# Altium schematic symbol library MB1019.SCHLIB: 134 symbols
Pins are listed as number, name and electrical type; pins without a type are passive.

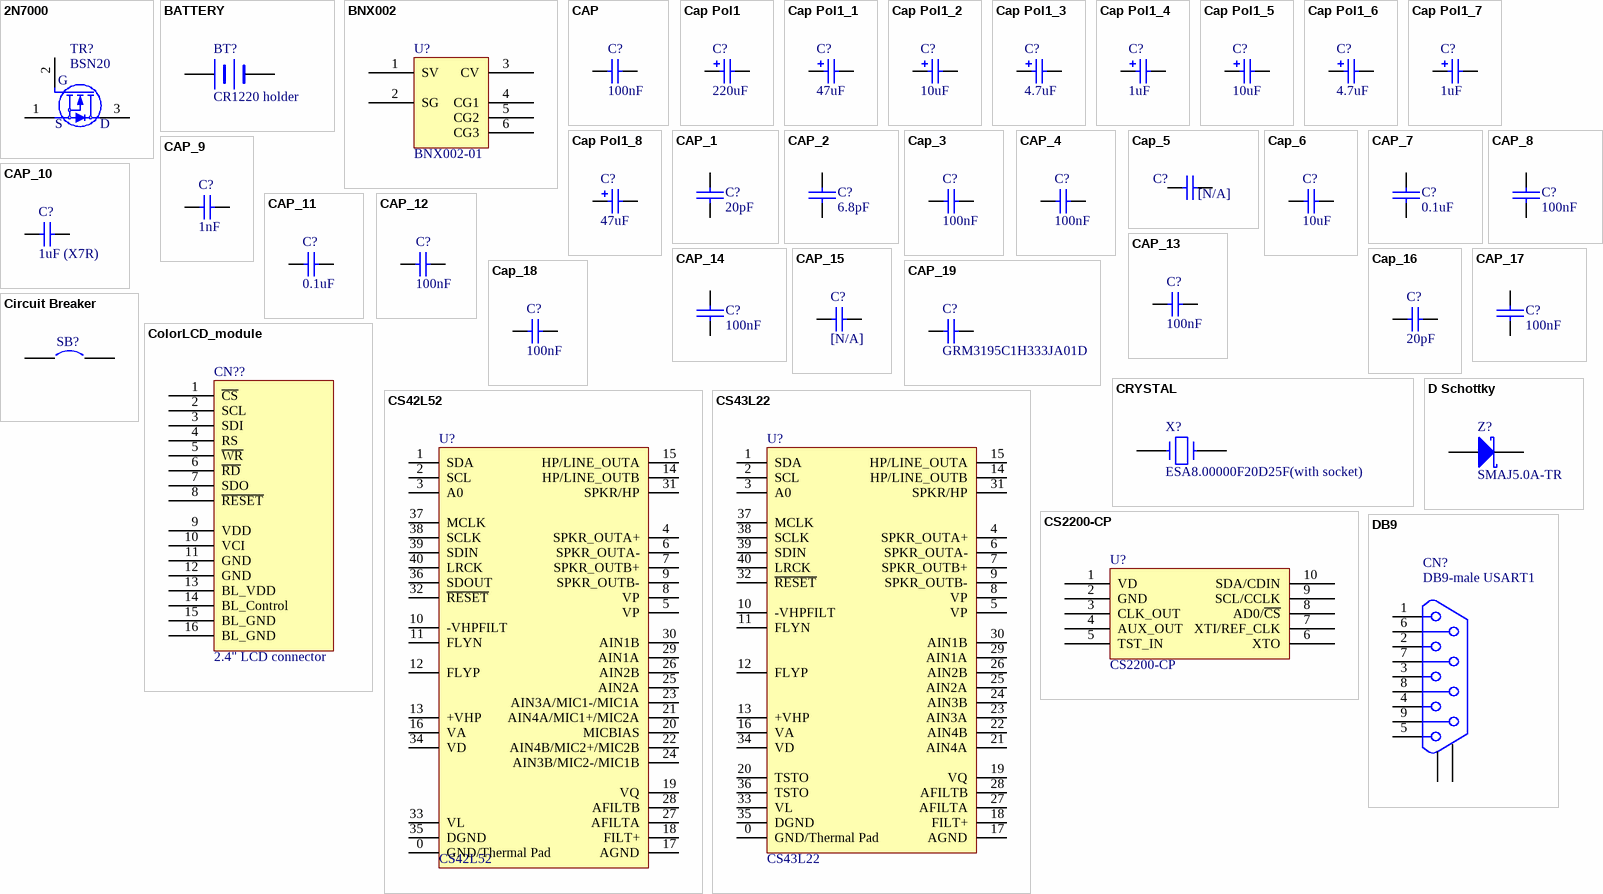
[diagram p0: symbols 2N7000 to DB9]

## 2N7000
designator TR?, comment BSN20
footprint SOT23-3L (Footprint not found)
footprint SOT-23
pins: 1 S, 2 G, 3 D

## BATTERY
designator BT?, comment CR1220 holder
Battery
footprint BATT (Footprint not found)
footprint LI1220_1
pins: 1 +, 2 -
2 alternate drawings of the same symbol

## BNX002
designator U?, comment BNX002-01
footprint BNX001 (Footprint not found)
pins: 1 SV, 2 SG, 3 CV, 4 CG1, 5 CG2, 6 CG3

## CAP
designator C?, comment 100nF
Capacitor; Value: 100pF
footprint RAD-0.3 (Capacitor; 2 Leads)
simulation model CAP (Capacitor)
signal-integrity model Cap
footprint CAPR5.08-7.8X3.2
footprint CAPR2.54-5.1X3.2
footprint 0603
footprint 0603P
footprint 0603C
footprint 0402C
pins: 1, 2

## Cap Pol1
designator C?, comment 220uF
Polarized Capacitor (Radial); Value: 47uF
simulation model CAP (Capacitor)
signal-integrity model C310M
footprint C310M (Footprint not found)
pins: 1, 2

## Cap Pol1_1
designator C?, comment 47uF
Polarized Capacitor (Radial); Value: 10uF
simulation model CAP (Capacitor)
signal-integrity model C200M
footprint C200M (Footprint not found)
pins: 1, 2

## Cap Pol1_2
designator C?, comment 10uF
Polarized Capacitor (Radial)
simulation model CAP (Capacitor)
signal-integrity model C200M
footprint 3528 (Footprint not found)
footprint TAN-A
pins: 1, 2

## Cap Pol1_3
designator C?, comment 4.7uF
Polarized Capacitor (Radial); Value: 100pF
simulation model CAP (Capacitor)
signal-integrity model Cap Pol
footprint Model Name (Footprint not found)
footprint TAN-A
pins: 1, 2

## Cap Pol1_4
designator C?, comment 1uF
Polarized Capacitor (Radial); Value: 10uF
simulation model CAP (Capacitor)
signal-integrity model Cap Pol
footprint 3528 (Footprint not found)
footprint TAN-B
footprint TAN-A
pins: 1, 2

## Cap Pol1_5
designator C?, comment 10uF
Polarized Capacitor (Radial)
simulation model CAP (Capacitor)
signal-integrity model C200M
footprint 3528 (Footprint not found)
footprint TAN-B
footprint TAN-A
pins: 1, 2

## Cap Pol1_6
designator C?, comment 4.7uF
Polarized Capacitor (Radial); Value: 100pF
simulation model CAP (Capacitor)
signal-integrity model 3528A
footprint 3528 (Footprint not found)
footprint TAN-B
footprint TAN-A
pins: 1, 2

## Cap Pol1_7
designator C?, comment 1uF
Polarized Capacitor (Radial); Value: 47uF
simulation model CAP (Capacitor)
signal-integrity model C310M
footprint C310M (Footprint not found)
footprint C160M
footprint TAN-A
pins: 1, 2

## Cap Pol1_8
designator C?, comment 47uF
Polarized Capacitor (Radial); Value: 100pF
simulation model CAP (Capacitor)
signal-integrity model Cap Pol
footprint TAN-B (Footprint not found)
pins: 1, 2

## CAP_1
designator C?, comment 20pF
Capacitor
footprint 0603 (Footprint not found)
footprint 0603C
pins: 1, 2
2 alternate drawings of the same symbol

## CAP_2
designator C?, comment 6.8pF
Capacitor
footprint 0603 (Footprint not found)
footprint 0603C
pins: 1, 2

## Cap_3
designator C?, comment 100nF
Capacitor; Value: 10nF
simulation model CAP (Capacitor)
signal-integrity model Cap
footprint 0603 (Footprint not found)
footprint 0402C
footprint 0603C
pins: 1, 2

## CAP_4
designator C?, comment 100nF
Capacitor; Value: 100pF
footprint RAD-0.3 (Capacitor; 2 Leads)
simulation model CAP (Capacitor)
signal-integrity model Cap
footprint CAPR5.08-7.8X3.2
footprint CAPR2.54-5.1X3.2
footprint 0603
footprint 0402C
footprint 0603C
pins: 1, 2

## Cap_5
designator C?, comment [N/A]
Capacitor; Value: 10nF
simulation model CAP (Capacitor)
signal-integrity model Cap
footprint 0603 (Footprint not found)
footprint 0603C (Footprint not found)
pins: 1, 2

## Cap_6
designator C?, comment 10uF
Capacitor; Value: 10nF
simulation model CAP (Capacitor)
signal-integrity model Cap
footprint 0603 (Footprint not found)
footprint 0402C
footprint 0805C (Footprint not found)
pins: 1, 2

## CAP_7
designator C?, comment 0.1uF
Capacitor
footprint 0603 (Footprint not found)
footprint 0603P
footprint 0603C (Footprint not found)
pins: 1, 2
2 alternate drawings of the same symbol

## CAP_8
designator C?, comment 100nF
Capacitor
footprint 0603 (Footprint not found)
footprint 0603C
footprint 0603C (Footprint not found)
pins: 1, 2
2 alternate drawings of the same symbol

## CAP_9
designator C?, comment 1nF
Capacitor; Value: 100pF
footprint RAD-0.3 (Capacitor; 2 Leads)
simulation model CAP (Capacitor)
signal-integrity model Cap
footprint CAPR5.08-7.8X3.2
footprint CAPR2.54-5.1X3.2
footprint 0603
footprint 0603C
pins: 1, 2

## CAP_10
designator C?, comment 1uF (X7R)
Capacitor; Value: 100nF
footprint RAD-0.3 (Capacitor; 2 Leads)
simulation model CAP (Capacitor)
signal-integrity model Cap
footprint CAPR5.08-7.8X3.2
footprint CAPR2.54-5.1X3.2
footprint 0603
footprint 0603P
footprint 0603C
pins: 1, 2

## CAP_11
designator C?, comment 0.1uF
Capacitor; Value: 100nF
footprint RAD-0.3 (Capacitor; 2 Leads)
simulation model CAP (Capacitor)
signal-integrity model Cap
footprint CAPR5.08-7.8X3.2
footprint CAPR2.54-5.1X3.2
footprint 0603
footprint 0603P
footprint 0402C
pins: 1, 2

## CAP_12
designator C?, comment 100nF
Capacitor; Value: 100pF
simulation model CAP (Capacitor)
signal-integrity model Cap
footprint 3528A (Footprint not found)
footprint 1307
footprint 0805
footprint 0603C
footprint 0402C
pins: 1, 2

## CAP_13
designator C?, comment 100nF
Capacitor; Value: 100pF
footprint RAD-0.3 (Capacitor; 2 Leads)
simulation model CAP (Capacitor)
signal-integrity model Cap
footprint CAPR5.08-7.8X3.2
footprint CAPR2.54-5.1X3.2
footprint 0603P (Footprint not found)
footprint 0402C
footprint 0603C
pins: 1, 2

## CAP_14
designator C?, comment 100nF
Capacitor
footprint 0603 (Footprint not found)
footprint 0603P
footprint 0402C
footprint 0603C
pins: 1, 2
2 alternate drawings of the same symbol

## CAP_15
designator C?, comment [N/A]
Capacitor; Value: 100pF
footprint RAD-0.3 (Capacitor; 2 Leads)
simulation model CAP (Capacitor)
signal-integrity model Cap
footprint CAPR5.08-7.8X3.2
footprint CAPR2.54-5.1X3.2
footprint 0603P (Footprint not found)
footprint 0603C
pins: 1, 2

## Cap_16
designator C?, comment value 20pF  (hidden comment: Cap)
Capacitor
footprint RAD-0.3
footprint VP32-3.2
footprint VP45-3.2
footprint 0603
footprint 0603R
pins: 1, 2
2 alternate drawings of the same symbol

## CAP_17
designator C?, comment 100nF
footprint 0603P
footprint 0402C
footprint 0603C
pins: 1, 2
2 alternate drawings of the same symbol

## Cap_18
designator C?, comment 100nF
Capacitor; Value: 10nF
footprint 0603
footprint 0603P
footprint 0402C
footprint 0603C
pins: 1, 2
2 alternate drawings of the same symbol

## CAP_19
designator C?, comment GRM3195C1H333JA01D
Capacitor; Value: 100pF
footprint RAD-0.3 (Capacitor; 2 Leads)
simulation model CAP (Capacitor)
signal-integrity model Cap
footprint CAPR5.08-7.8X3.2
footprint CAPR2.54-5.1X3.2
footprint 0603P (Footprint not found)
footprint 1206C
pins: 1, 2

## Circuit Breaker
designator SB?
Circuit Breaker
footprint SPST-2 (Circuit Breaker; 2 Leads)
footprint JP2_SMD
pins: 1, 2

## ColorLCD_module
designator CN??, comment 2.4" LCD connector
footprint AM240320A (Footprint not found)
footprint MB989 (Footprint not found)
pins: 1 ~{CS}, 2 SCL, 3 SDI, 4 RS, 5 ~{WR}, 6 ~{RD}, 7 SDO, 8 ~{RESET}, 9 VDD, 10 VCI, 11 GND, 12 GND, 13 BL_VDD, 14 BL_Control, 15 BL_GND, 16 BL_GND

## CRYSTAL
designator X?, comment ESA8.00000F20D25F(with socket)
Crystal
footprint XTAL1 (Footprint not found)
footprint XTAL_socket
pins: 1, 2
2 alternate drawings of the same symbol

## CS42L52
designator U?
footprint QFN40 (Footprint not found)
footprint QFN40(6*6)
pins: 0 GND/Thermal Pad, 1 SDA, 2 SCL, 3 A0, 4 SPKR_OUTA+, 5 VP, 6 SPKR_OUTA-, 7 SPKR_OUTB+, 8 VP, 9 SPKR_OUTB-, 10 -VHPFILT, 11 FLYN, 12 FLYP, 13 +VHP, 14 HP/LINE_OUTB, 15 HP/LINE_OUTA, 16 VA, 17 AGND, 18 FILT+, 19 VQ, 20 MICBIAS, 21 AIN4A/MIC1+/MIC2A, 22 AIN4B/MIC2+/MIC2B, 23 AIN3A/MIC1-/MIC1A, 24 AIN3B/MIC2-/MIC1B, 25 AIN2A, 26 AIN2B, 27 AFILTA, 28 AFILTB, 29 AIN1A, 30 AIN1B, 31 SPKR/HP, 32 ~{RESET}, 33 VL, 34 VD, 35 DGND, 36 SDOUT, 37 MCLK, 38 SCLK, 39 SDIN, 40 LRCK

## CS43L22
designator U?
footprint QFN40 (Footprint not found)
footprint QFN40(6*6)
pins: 0 GND/Thermal Pad, 1 SDA, 2 SCL, 3 A0, 4 SPKR_OUTA+, 5 VP, 6 SPKR_OUTA-, 7 SPKR_OUTB+, 8 VP, 9 SPKR_OUTB-, 10 -VHPFILT, 11 FLYN, 12 FLYP, 13 +VHP, 14 HP/LINE_OUTB, 15 HP/LINE_OUTA, 16 VA, 17 AGND, 18 FILT+, 19 VQ, 20 TSTO, 21 AIN4A, 22 AIN4B, 23 AIN3A, 24 AIN3B, 25 AIN2A, 26 AIN2B, 27 AFILTA, 28 AFILTB, 29 AIN1A, 30 AIN1B, 31 SPKR/HP, 32 ~{RESET}, 33 VL, 34 VD, 35 DGND, 36 TSTO, 37 MCLK, 38 SCLK, 39 SDIN, 40 LRCK

## CS2200-CP
designator U?
pins: 1 VD, 2 GND, 3 CLK_OUT, 4 AUX_OUT, 5 TST_IN, 6 XTO, 7 XTI/REF_CLK, 8 AD0/~{CS}, 9 SCL/CCLK, 10 SDA/CDIN

## D Schottky
designator Z?, comment SMAJ5.0A-TR
Schottky Diode; Code - JEDEC: DO-214-AA
footprint 1R1C (Footprint not found)
pins: 1 A, 2 K

## DB9
designator CN?, comment DB9-male USART1
footprint DB9/M (Footprint not found)
pins: 0, 0 10, 1, 2, 3, 4, 5, 6, 7, 8, 9
2 alternate drawings of the same symbol

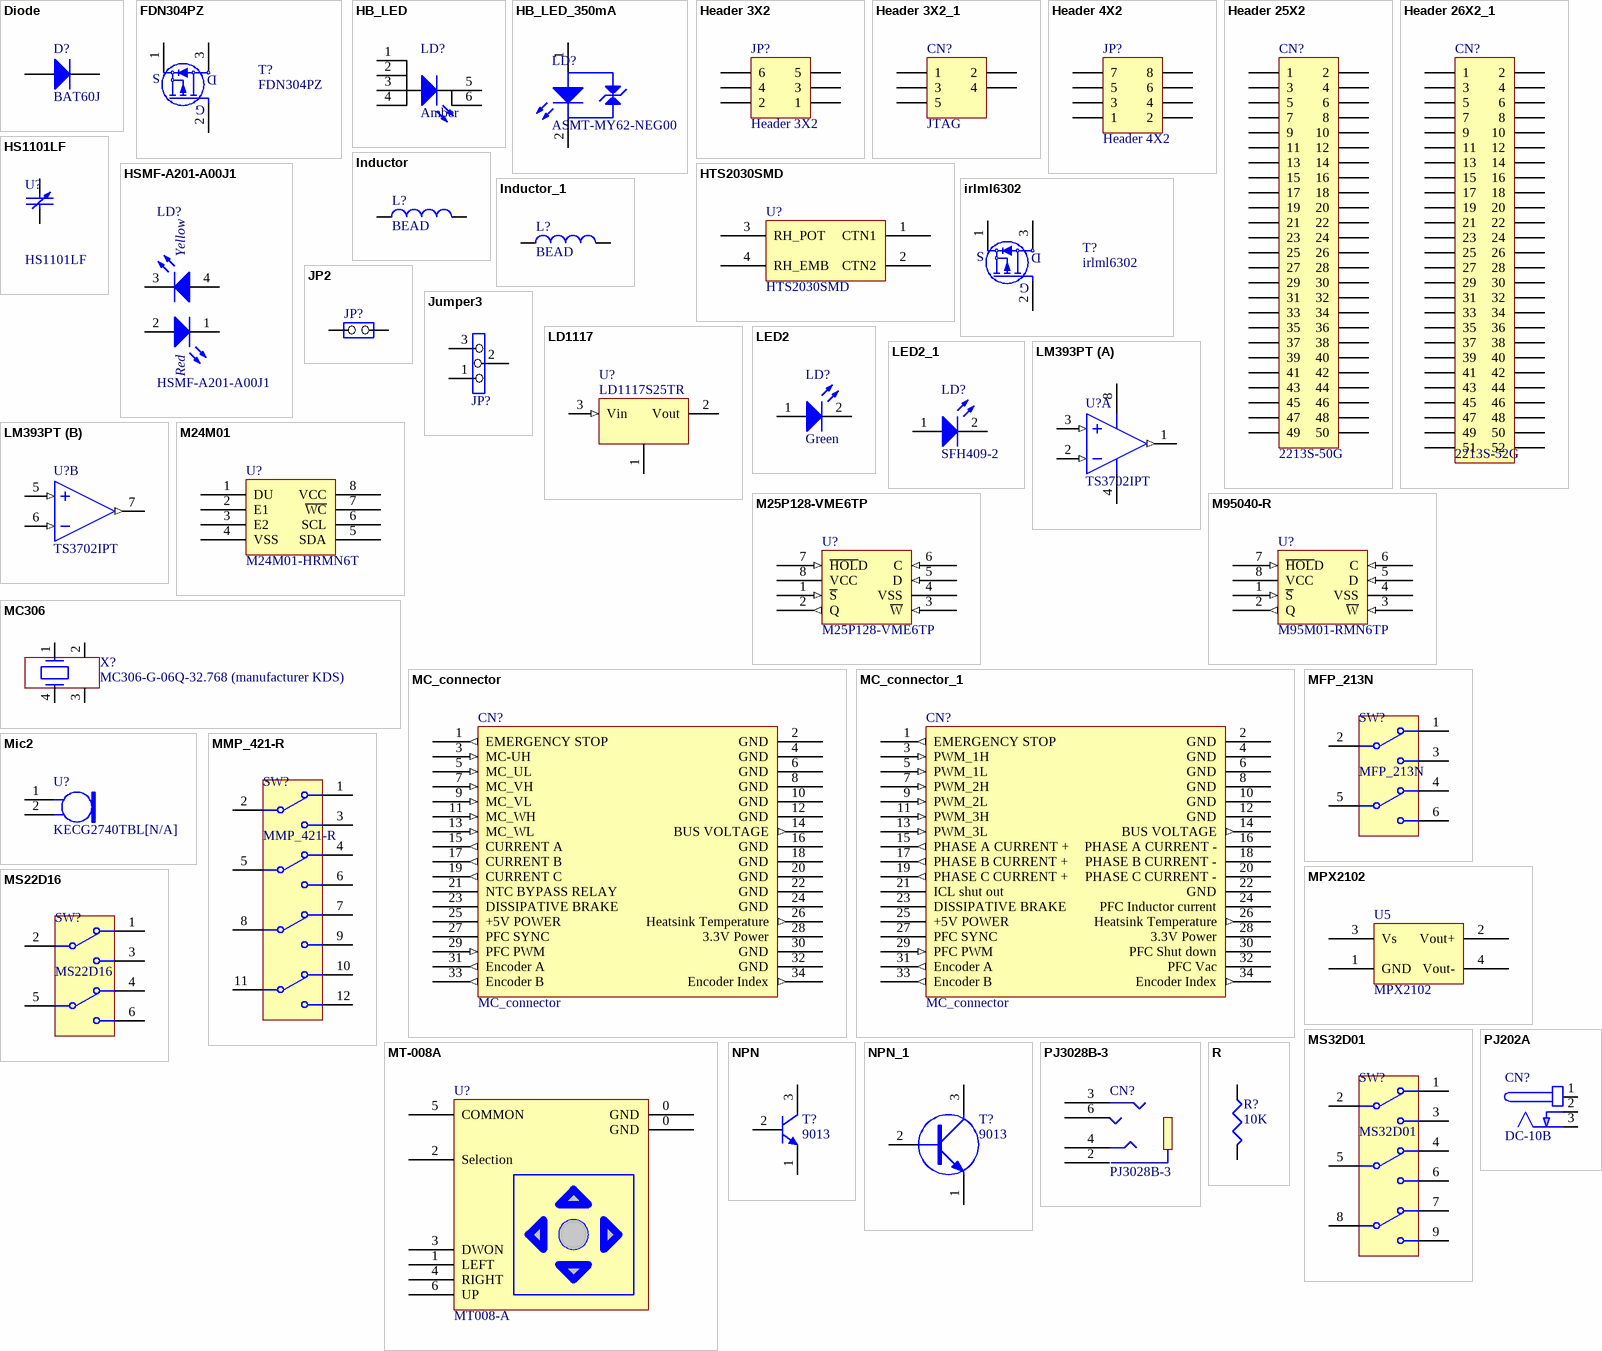
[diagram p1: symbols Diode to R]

## Diode
designator D?, comment BAT60J
Default Diode; Code - JEDEC: DO-214-AB
footprint DSO-C2/X3.3 (DO-214-AB/SMC; 2 C-Bend Leads; Body 7.9 x 5.9 mm, inc. leads (LxW))
simulation model DIODE (Diode)
signal-integrity model Diode
footprint SOD-323 (Footprint not found)
pins: 1 A, 2 K

## FDN304PZ
designator T?
footprint Model Name (Footprint not found)
footprint SOT-23 (Footprint not found)
pins: 1 S, 2 G, 3 D

## HB_LED
designator LD?, comment Amber
High brightness LED
footprint PLCC-4 (Footprint not found)
pins: 1 A, 2 A, 3 A, 4 A, 5 K, 6 K

## HB_LED_350mA
designator LD?, comment ASMT-MY62-NEG00
High brightness LED
footprint HB_LED (Footprint not found)
pins: 1 A, 2 K

## Header 3X2
designator JP?
Header, 3-Pin, Dual row
footprint HDR2X3 (Connector; Header; 3x2 Position)
signal-integrity model Connector
footprint 2*3P
pins: 1, 2, 3, 4, 5, 6

## Header 3X2_1
designator CN?, comment JTAG
Header, 3-Pin, Dual row
footprint HDR2X3 (Connector; Header; 3x2 Position)
signal-integrity model Connector
footprint 2*3P
pins: 1, 2, 3, 4, 5

## Header 4X2
designator JP?
Header, 4-Pin, Dual row
footprint HDR2X4 (Connector; Header; 4x2 Position)
signal-integrity model Connector
footprint 2*4P
pins: 1, 2, 3, 4, 5, 6, 7, 8

## Header 25X2
designator CN?, comment 2213S-50G
Header, 25-Pin, Dual row
footprint 2*25P (Footprint not found)
signal-integrity model Connector
pins: 1, 2, 3, 4, 5, 6, 7, 8, 9, 10, 11, 12, 13, 14, 15, 16, 17, 18, 19, 20, 21, 22, 23, 24, 25, 26, 27, 28, 29, 30, 31, 32, 33, 34, 35, 36, 37, 38, 39, 40, 41, 42, 43, 44, 45, 46, 47, 48, 49, 50

## Header 26X2_1
designator CN?, comment 2213S-52G
Header, 26-Pin, Dual row
footprint 2*26P (Footprint not found)
signal-integrity model Connector
pins: 1, 2, 3, 4, 5, 6, 7, 8, 9, 10, 11, 12, 13, 14, 15, 16, 17, 18, 19, 20, 21, 22, 23, 24, 25, 26, 27, 28, 29, 30, 31, 32, 33, 34, 35, 36, 37, 38, 39, 40, 41, 42, 43, 44, 45, 46, 47, 48, 49, 50, 51, 52

## HS1101LF
designator U?
footprint CAP1101 (Footprint not found)
pins: 1, 2

## HSMF-A201-A00J1
designator LD?
footprint led (Footprint not found)
footprint LED2-28*32
pins: 1 RED_cathode, 2 Red_anode, 3 YellowGreen_cathode, 4 YellowGreen_anode

## HTS2030SMD
designator U?
footprint 2030SMD (Footprint not found)
pins: 1 CTN1, 2 CTN2, 3 RH_POT, 4 RH_EMB

## Inductor
designator L?, comment BEAD
Inductor; Value: 100uH
footprint 0603 (Footprint not found)
footprint 0603C
footprint 0603L
pins: 1, 2

## Inductor_1
designator L?, comment BEAD
Inductor; Value: 100uH
footprint 0603 (Footprint not found)
footprint 0603L
pins: 1, 2

## irlml6302
designator T?
footprint Model Name (Footprint not found)
footprint SOT-23 (Footprint not found)
pins: 1 S, 2 G, 3 D

## JP2
designator JP?
footprint SIP2 (Footprint not found)
pins: 1 COMMON, 2 NO

## Jumper3
designator JP?
footprint SIP3 (Footprint not found)
pins: 1, 2, 3

## LD1117
designator U?, comment LD1117S25TR
footprint SOT-223
pins: 1, 2 Vout (power), 3 Vin (in)
2 alternate drawings of the same symbol

## LED2
designator LD?, comment Green
Typical RED, GREEN, YELLOW, AMBER GaAs LED
footprint D0603 (Footprint not found)
footprint 0603D
pins: 1 A, 2 K

## LED2_1
designator LD?, comment SFH409-2
Typical RED, GREEN, YELLOW, AMBER GaAs LED
footprint D0603 (Footprint not found)
footprint D0.1L
pins: 1 A, 2 K

## LM393PT
designator U?, comment TS3702IPT
footprint TSSOP8 (Footprint not found)
footprint TSSOP8(6.4)
part A pins: 1 OUT (out), 2 IN- (in), 3 IN+ (in), 4 V- (power), 8 V+ (power)
part B pins: 5 IN+ (in), 6 IN- (in), 7 OUT (out)

## M24M01
designator U?, comment M24M01-HRMN6T
footprint SO8 (Footprint not found)
pins: 1 DU, 2 E1, 3 E2, 4 VSS, 5 SDA, 6 SCL, 7 ~{WC}, 8 VCC

## M25P128-VME6TP
designator U?
footprint VDFPN8(8*6) (Footprint not found)
footprint TSSOP8 (Shrink Small Outline, Plastic, Thin; 8 Leads; Body Width 4.4 mm; Pitch 0.65 mm)
footprint SO8N (Footprint not found)
footprint SO8
pins: 1 ~{S} (in), 2 Q (out), 3 ~{W} (in), 4 VSS (power), 5 D (in), 6 C (in), 7 ~{HOL}D (in), 8 VCC (power)

## M95040-R
designator U?, comment M95M01-RMN6TP
footprint VDFPN8(8*6) (Footprint not found)
footprint TSSOP8 (Shrink Small Outline, Plastic, Thin; 8 Leads; Body Width 4.4 mm; Pitch 0.65 mm)
footprint SO8N (Footprint not found)
footprint SO8
pins: 1 ~{S} (in), 2 Q (out), 3 ~{W} (in), 4 VSS (power), 5 D (in), 6 C (in), 7 ~{HOL}D (in), 8 VCC (power)

## MC306
designator X?, comment MC306-G-06Q-32.768 (manufacturer KDS)
footprint SM8 (Footprint not found)
pins: 1, 2, 3, 4

## MC_connector
designator CN?
footprint IDC34S (Footprint not found)
pins: 1 EMERGENCY STOP (out), 2 GND (power), 3 MC-UH (in), 4 GND (power), 5 MC_UL (in), 6 GND (power), 7 MC_VH (in), 8 GND (power), 9 MC_VL (in), 10 GND (power), 11 MC_WH (in), 12 GND (power), 13 MC_WL (in), 14 BUS VOLTAGE (out), 15 CURRENT A (out), 16 GND (power), 17 CURRENT B (out), 18 GND (power), 19 CURRENT C (out), 20 GND (power), 21 NTC BYPASS RELAY, 22 GND (power), 23 DISSIPATIVE BRAKE, 24 GND (power), 25 +5V POWER (power), 26 Heatsink Temperature (out), 27 PFC SYNC, 28 3.3V Power (power), 29 PFC PWM (in), 30 GND (power), 31 Encoder A (out), 32 GND (power), 33 Encoder B (out), 34 Encoder Index (out)

## MC_connector_1
designator CN?, comment MC_connector
footprint IDC34S (Footprint not found)
pins: 1 EMERGENCY STOP (out), 2 GND (power), 3 PWM_1H (in), 4 GND (power), 5 PWM_1L (in), 6 GND (power), 7 PWM_2H (in), 8 GND (power), 9 PWM_2L (in), 10 GND (power), 11 PWM_3H (in), 12 GND (power), 13 PWM_3L (in), 14 BUS VOLTAGE (out), 15 PHASE A CURRENT + (out), 16 PHASE A CURRENT - (power), 17 PHASE B CURRENT + (out), 18 PHASE B CURRENT - (power), 19 PHASE C CURRENT + (out), 20 PHASE C CURRENT - (power), 21 ICL shut out, 22 GND (power), 23 DISSIPATIVE BRAKE, 24 PFC Inductor current, 25 +5V POWER (power), 26 Heatsink Temperature (out), 27 PFC SYNC, 28 3.3V Power (power), 29 PFC PWM (in), 30 PFC Shut down, 31 Encoder A (out), 32 PFC Vac, 33 Encoder B (out), 34 Encoder Index (out)

## MFP_213N
designator SW?
SPDT Subminiature Toggle Switch, Right Angle Mounting, Vertical Actuation; Revision 1: Jul-2002: Re-released for DXP Platform.; Revision 2: 17-Dec-2003: Schematic revised, PCB Footprint replaced.
pins: 1, 2, 3, 4, 5, 6

## Mic2
designator U?, comment KECG2740TBL[N/A]
Microphone
footprint KEC2740 (Footprint not found)
pins: 1, 2

## MMP_421-R
designator SW?
SPDT Subminiature Toggle Switch, Right Angle Mounting, Vertical Actuation; Revision 1: Jul-2002: Re-released for DXP Platform.; Revision 2: 17-Dec-2003: Schematic revised, PCB Footprint replaced.
pins: 1, 2, 3, 4, 5, 6, 7, 8, 9, 10, 11, 12

## MPX2102
designator U5
footprint MPAK (Footprint not found)
pins: 1 GND, 2 Vout+, 3 Vs, 4 Vout-

## MS22D16
designator SW?
DPDT; Revision 1: Jul-2002: Re-released for DXP Platform.; Revision 2: 17-Dec-2003: Schematic revised, PCB Footprint replaced.
footprint 6-pin switch (Footprint not found)
pins: 1, 2, 3, 4, 5, 6

## MS32D01
designator SW?
3P2T; Revision 1: Jul-2002: Re-released for DXP Platform.; Revision 2: 17-Dec-2003: Schematic revised, PCB Footprint replaced.
footprint 9-pin switch (Footprint not found)
pins: 1, 2, 3, 4, 5, 6, 7, 8, 9

## MT-008A
designator U?, comment MT008-A
footprint JOY (Footprint not found)
pins: 0 GND, 0 GND, 1 LEFT, 2 Selection, 3 DWON, 4 RIGHT, 5 COMMON, 6 UP

## NPN
designator T?, comment 9013
NPN Bipolar Transistor; Code - JEDEC: TO-226-AA
footprint BCY-W3 (TO, Flat Index; 3 In-Line, Axial Leads; Body Dia. 4.8mm)
simulation model NPN
signal-integrity model NPN
footprint SOT-23
pins: 1 E, 2 B, 3 C

## NPN_1
designator T?, comment 9013
footprint SOT-23
pins: 1 E, 2 B, 3 C

## PJ202A
designator CN?, comment DC-10B
footprint DC10B (Footprint not found)
pins: 1 +, 2 GND, 3 GND

## PJ3028B-3
designator CN?
pins: 2, 3, 4, 6

## R
designator R?, comment 10K
Right: 20; Bottom: 30
footprint 0402R (Footprint not found)
footprint 0603R
pins: 1, 2
2 alternate drawings of the same symbol

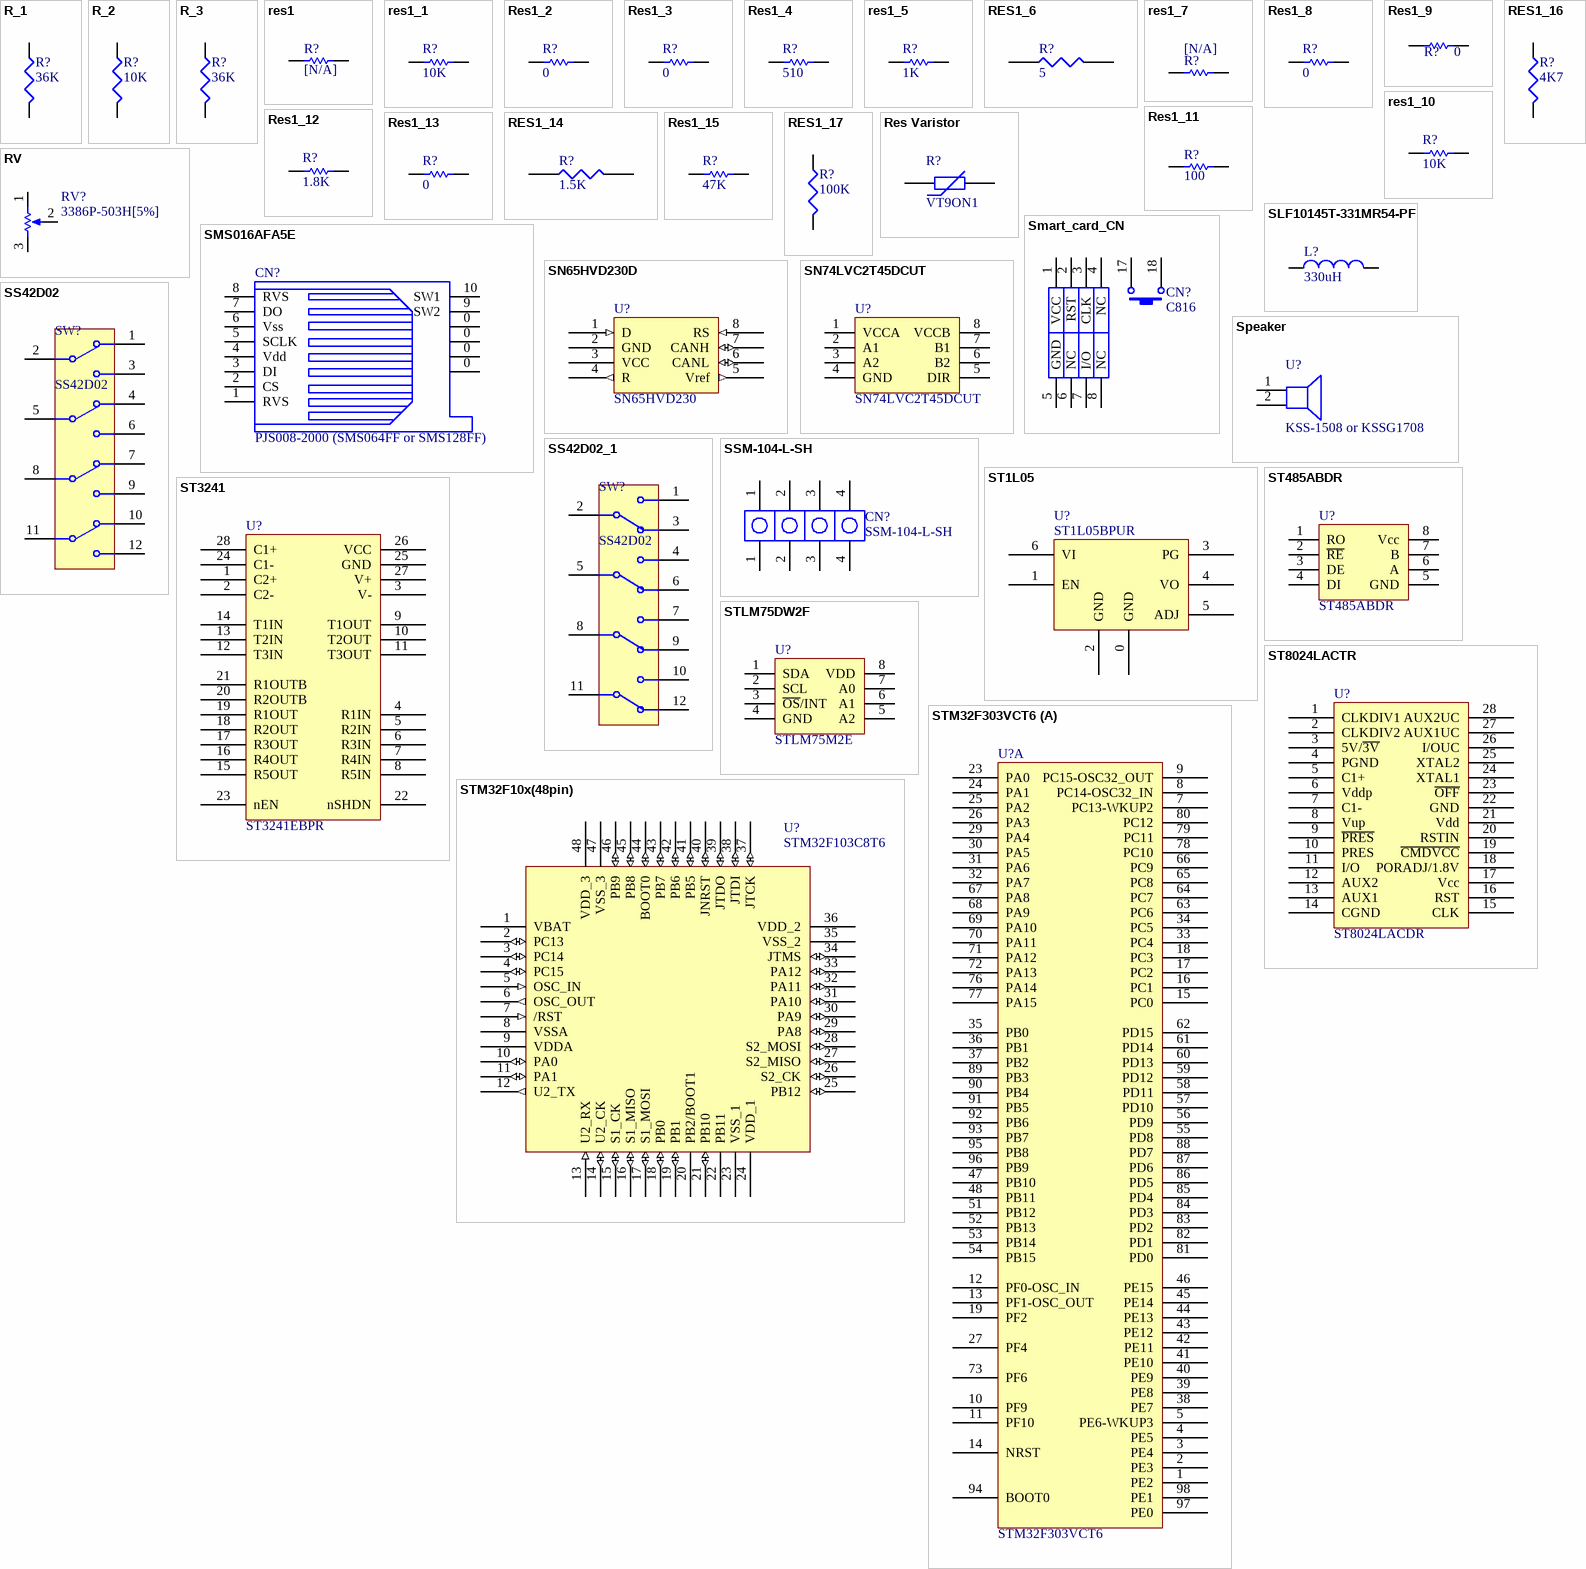
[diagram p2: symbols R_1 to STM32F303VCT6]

## R_1
designator R?, comment 36K
Right: 20; Bottom: 30
footprint 0603R (Footprint not found)
pins: 1, 2
2 alternate drawings of the same symbol

## R_2
designator R?, comment 10K
Right: 20; Bottom: 30
footprint 0603 (Footprint not found)
footprint 0402R
footprint 0603R
pins: 1, 2
2 alternate drawings of the same symbol

## R_3
designator R?, comment 36K
Right: 20; Bottom: 30
footprint 0603 (Footprint not found)
footprint 0603R
pins: 1, 2
2 alternate drawings of the same symbol

## res1
designator R?, comment [N/A]
Resistor; Value: 1K
footprint AXIAL-0.3 (Resistor; 2 Leads)
simulation model RESISTOR (Resistor)
signal-integrity model Res
footprint 0603 (Footprint not found)
footprint 0603R
pins: 1, 2
1 alternate drawing of the same symbol

## res1_1
designator R?, comment 10K
Resistor; Value: 1K
footprint AXIAL-0.3 (Resistor; 2 Leads)
simulation model RESISTOR (Resistor)
signal-integrity model Res
footprint 0603
footprint 0603R
footprint 0402R
pins: 1, 2
1 alternate drawing of the same symbol

## Res1_2
designator R?, comment 0
Resistor; Value: 1K
footprint AXIAL-0.3 (Resistor; 2 Leads)
simulation model RESISTOR (Resistor)
signal-integrity model Res
footprint 0603
footprint 0805
footprint 0603R
pins: 1, 2
1 alternate drawing of the same symbol

## Res1_3
designator R?, comment 0
Resistor; Value: 1K
footprint AXIAL-0.3 (Resistor; 2 Leads)
simulation model RESISTOR (Resistor)
signal-integrity model Res
footprint 0603
footprint 0603 (Footprint not found)
footprint 0603R
pins: 1, 2
1 alternate drawing of the same symbol

## Res1_4
designator R?, comment 510
Resistor; Value: 1K
footprint AXIAL-0.3 (Resistor; 2 Leads)
simulation model RESISTOR (Resistor)
signal-integrity model Res
footprint 0603
footprint 0805
footprint 0402R
footprint 0603R
pins: 1, 2
1 alternate drawing of the same symbol

## res1_5
designator R?, comment 1K
Resistor
footprint AXIAL-0.3 (Resistor; 2 Leads)
footprint 0805
footprint 0603
footprint 0402R
footprint 0603R
pins: 1, 2
1 alternate drawing of the same symbol

## RES1_6
designator R?, comment 5
footprint 0603 (Footprint not found)
footprint 0603R
pins: 1, 2
2 alternate drawings of the same symbol

## res1_7
designator R?, comment [N/A]
Resistor; Value: 1K
footprint AXIAL-0.3 (Resistor; 2 Leads)
simulation model RESISTOR (Resistor)
signal-integrity model Res
footprint 0603
footprint 0603_NC
footprint 0603R
pins: 1, 2
1 alternate drawing of the same symbol

## Res1_8
designator R?, comment 0
Resistor; Value: 1K
footprint AXIAL-0.3 (Resistor; 2 Leads)
simulation model RESISTOR (Resistor)
signal-integrity model Res
footprint 0805
footprint 0805 (Footprint not found)
footprint 0603R
pins: 1, 2
1 alternate drawing of the same symbol

## Res1_9
designator R?, comment 0
Resistor; Value: 1K
simulation model RESISTOR (Resistor)
signal-integrity model Res
footprint 0603 (Footprint not found)
footprint 0603R
pins: 1, 2
1 alternate drawing of the same symbol

## res1_10
designator R?, comment 10K
Resistor; Value: 1K
footprint AXIAL-0.3 (Resistor; 2 Leads)
simulation model RESISTOR (Resistor)
signal-integrity model Res
footprint 0603
footprint 0402R
pins: 1, 2
1 alternate drawing of the same symbol

## Res1_11
designator R?, comment 100
Resistor; Value: 1K
footprint AXIAL-0.3 (Resistor; 2 Leads)
simulation model RESISTOR (Resistor)
signal-integrity model Res
footprint 0603
footprint 0603 (Footprint not found)
footprint 0603R
footprint 0402R
pins: 1, 2
1 alternate drawing of the same symbol

## Res1_12
designator R?, comment 1.8K
Resistor; Value: 1K
footprint AXIAL-0.3 (Resistor; 2 Leads)
simulation model RESISTOR (Resistor)
signal-integrity model Res
footprint 0603
footprint 0603 (Footprint not found)
footprint 0603R
footprint 0603R (Footprint not found)
pins: 1, 2
1 alternate drawing of the same symbol

## Res1_13
designator R?, comment 0
Resistor; Value: 1K
footprint AXIAL-0.3 (Resistor; 2 Leads)
simulation model RESISTOR (Resistor)
signal-integrity model Res
footprint 0603
footprint 0805
footprint 0805R
footprint 0603R
pins: 1, 2
1 alternate drawing of the same symbol

## RES1_14
designator R?, comment 1.5K
footprint 0603R (Footprint not found)
pins: 1, 2
2 alternate drawings of the same symbol

## Res1_15
designator R?, comment 47K
Resistor; Value: 1K
footprint AXIAL-0.3 (Resistor; 2 Leads)
simulation model RESISTOR (Resistor)
signal-integrity model Res
footprint 0402R (Footprint not found)
footprint 0603R
pins: 1, 2
1 alternate drawing of the same symbol

## RES1_16
designator R?, comment 4K7
footprint 0603
footprint 0402R
footprint 0603R
pins: 1, 2

## RES1_17
designator R?, comment 100K
footprint 0603
footprint 0603R
pins: 1, 2

## Res Varistor
designator R?, comment VT9ON1
Varistor (Voltage-Sensitive Resistor)
footprint VT9ON1 (Footprint not found)
footprint PVT901
pins: 1, 2

## RV
designator RV?, comment 3386P-503H[5%]
footprint ADJRH (Footprint not found)
footprint 3296W
pins: 1 BOT, 2 TAP, 3 TOP

## SLF10145T-331MR54-PF
designator L?, comment 330uH
Inductor; Value: 100uH
footprint SLF_10145 (Footprint not found)
pins: 1, 2

## Smart_card_CN
designator CN?, comment C816
footprint SAM(C816) (Footprint not found)
pins: 1 VCC, 2 RST, 3 CLK, 4 NC, 5 GND, 6 NC, 7 I/O, 8 NC, 17, 18

## SMS016AFA5E
designator CN?, comment PJS008-2000 (SMS064FF or SMS128FF)
footprint MSD(PJS008) (Footprint not found)
pins: 0, 0, 0, 0, 1 RVS, 2 CS, 3 DI, 4 Vdd, 5 SCLK, 6 Vss, 7 DO, 8 RVS, 9 SW2, 10 SW1

## SN65HVD230D
designator U?, comment SN65HVD230
footprint SO8 (Small Outline; 8 Leads; Body Width 3.9 mm; Pitch 1.27 mm)
pins: 1 D (in), 2 GND (power), 3 VCC (power), 4 R (out), 5 Vref (out), 6 CANL (io), 7 CANH (io), 8 RS (in)

## SN74LVC2T45DCUT
designator U?
footprint VSSOP8 (Footprint not found)
pins: 1 VCCA, 2 A1, 3 A2, 4 GND, 5 DIR, 6 B2, 7 B1, 8 VCCB

## Speaker
designator U?, comment KSS-1508 or KSSG1708
Loudspeaker
footprint KS1508 (Footprint not found)
footprint KS1708
pins: 1 +, 2 -

## SS42D02
designator SW?
SPDT Subminiature Toggle Switch, Right Angle Mounting, Vertical Actuation; Revision 1: Jul-2002: Re-released for DXP Platform.; Revision 2: 17-Dec-2003: Schematic revised, PCB Footprint replaced.
pins: 1, 2, 3, 4, 5, 6, 7, 8, 9, 10, 11, 12

## SS42D02_1
designator SW?, comment SS42D02
SPDT Subminiature Toggle Switch, Right Angle Mounting, Vertical Actuation; Revision 1: Jul-2002: Re-released for DXP Platform.; Revision 2: 17-Dec-2003: Schematic revised, PCB Footprint replaced.
pins: 1, 2, 3, 4, 5, 6, 7, 8, 9, 10, 11, 12

## SSM-104-L-SH
designator CN?
footprint SSM-104-L-SH (Footprint not found)
pins: 1, 1, 2, 2, 3, 3, 4, 4

## ST1L05
designator U?, comment ST1L05BPUR
footprint DFN6
footprint DFN6(3X3)
pins: 0 GND, 1 EN, 2 GND, 3 PG, 4 VO, 5 ADJ, 6 VI
2 alternate drawings of the same symbol

## ST485ABDR
designator U?
footprint SO-8 (Footprint not found)
footprint SO8
pins: 1 RO, 2 ~{RE}, 3 DE, 4 DI, 5 GND, 6 A, 7 B, 8 Vcc

## ST3241
designator U?, comment ST3241EBPR
footprint SSOP28 (Footprint not found)
pins: 1 C2+, 2 C2-, 3 V-, 4 R1IN, 5 R2IN, 6 R3IN, 7 R4IN, 8 R5IN, 9 T1OUT, 10 T2OUT, 11 T3OUT, 12 T3IN, 13 T2IN, 14 T1IN, 15 R5OUT, 16 R4OUT, 17 R3OUT, 18 R2OUT, 19 R1OUT, 20 R2OUTB, 21 R1OUTB, 22 nSHDN, 23 nEN, 24 C1-, 25 GND, 26 VCC, 27 V+, 28 C1+
2 alternate drawings of the same symbol

## ST8024LACTR
designator U?, comment ST8024LACDR
footprint SO28 (Footprint not found)
pins: 1 CLKDIV1, 2 CLKDIV2, 3 5V/~{3V}, 4 PGND, 5 C1+, 6 Vddp, 7 C1-, 8 Vup, 9 ~{PRES}, 10 PRES, 11 I/O, 12 AUX2, 13 AUX1, 14 CGND, 15 CLK, 16 RST, 17 Vcc, 18 PORADJ/1.8V, 19 ~{CMDVCC}, 20 RSTIN, 21 Vdd, 22 GND, 23 ~{OFF}, 24 XTAL1, 25 XTAL2, 26 I/OUC, 27 AUX1UC, 28 AUX2UC

## STLM75DW2F
designator U?, comment STLM75M2E
footprint SO8 (Footprint not found)
pins: 1 SDA, 2 SCL, 3 ~{OS}/INT, 4 GND, 5 A2, 6 A1, 7 A0, 8 VDD

## STM32F10x(48pin)
designator U?, comment STM32F103C8T6
footprint TQ48
footprint LQFP48
pins: 1 VBAT (power), 2 PC13 (io), 3 PC14 (io), 4 PC15 (io), 5 OSC_IN (in), 6 OSC_OUT (out), 7 /RST (in), 8 VSSA, 9 VDDA (power), 10 PA0 (io), 11 PA1 (io), 12 U2_TX (out), 13 U2_RX (in), 14 U2_CK (io), 15 S1_CK (io), 16 S1_MISO (io), 17 S1_MOSI (io), 18 PB0 (io), 19 PB1 (io), 20 PB2/BOOT1, 21 PB10 (io), 22 PB11, 23 VSS_1, 24 VDD_1 (power), 25 PB12 (io), 26 S2_CK (io), 27 S2_MISO (io), 28 S2_MOSI (io), 29 PA8 (io), 30 PA9 (io), 31 PA10 (io), 32 PA11 (io), 33 PA12 (io), 34 JTMS (io), 35 VSS_2, 36 VDD_2 (power), 37 JTCK (io), 38 JTDI (io), 39 JTDO (io), 40 JNRST (io), 41 PB5 (io), 42 PB6 (io), 43 PB7 (io), 44 BOOT0 (io), 45 PB8 (io), 46 PB9 (io), 47 VSS_3, 48 VDD_3 (power)
2 alternate drawings of the same symbol

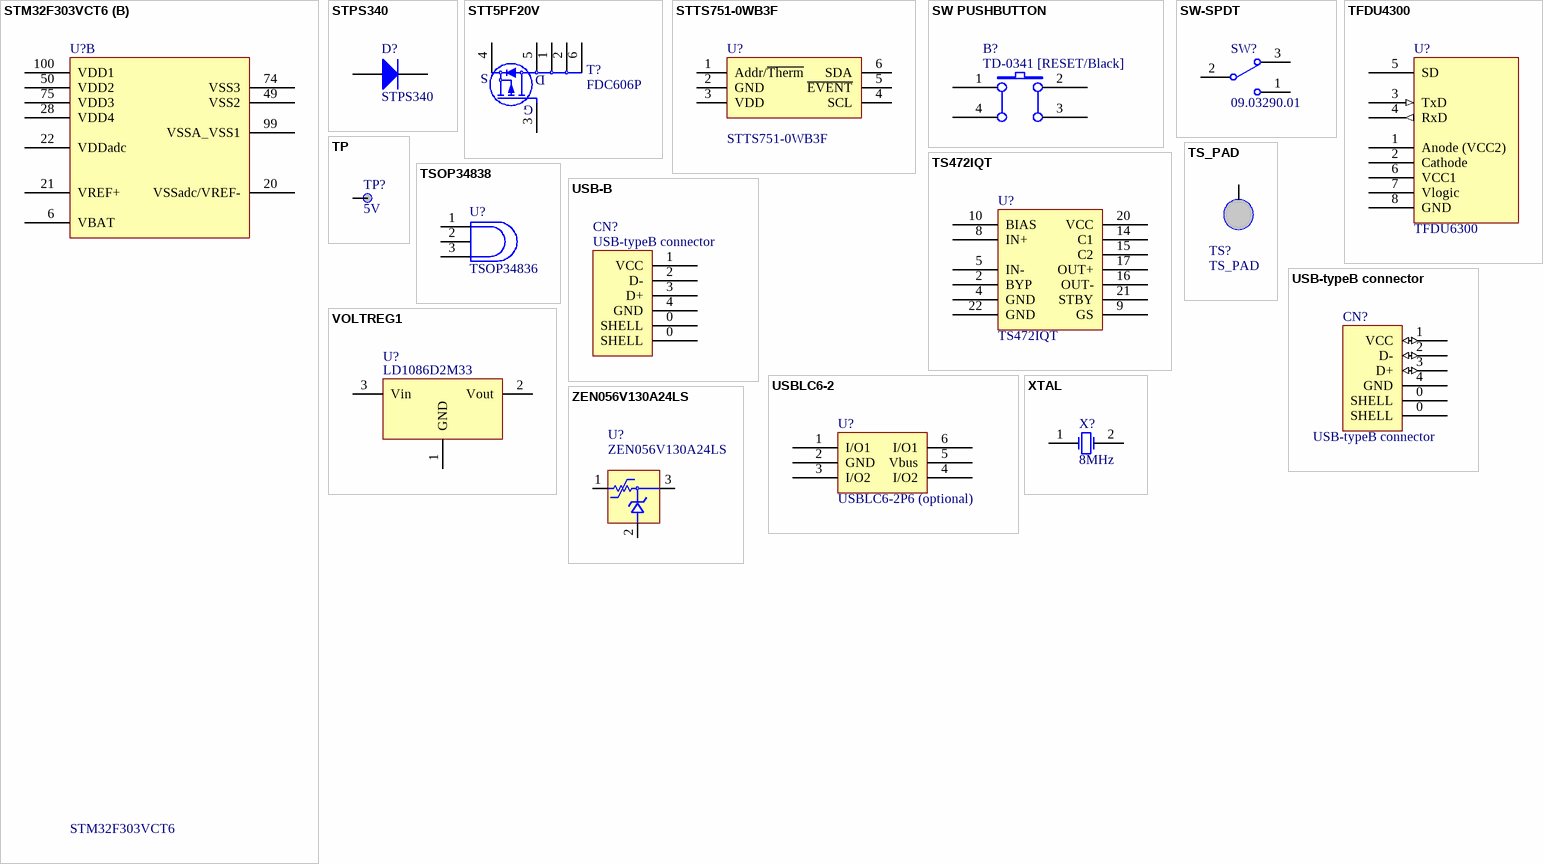
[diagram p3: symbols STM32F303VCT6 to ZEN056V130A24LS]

## STM32F303VCT6
designator U?
footprint LQFP100 (Footprint not found)
footprint TQ100_TOOL
footprint IC149-100-025-B5
part A pins: 1 PE2, 2 PE3, 3 PE4, 4 PE5, 5 PE6-WKUP3, 7 PC13-WKUP2, 8 PC14-OSC32_IN, 9 PC15-OSC32_OUT, 10 PF9, 11 PF10, 12 PF0-OSC_IN, 13 PF1-OSC_OUT, 14 NRST, 15 PC0, 16 PC1, 17 PC2, 18 PC3, 19 PF2, 23 PA0, 24 PA1, 25 PA2, 26 PA3, 27 PF4, 29 PA4, 30 PA5, 31 PA6, 32 PA7, 33 PC4, 34 PC5, 35 PB0, 36 PB1, 37 PB2, 38 PE7, 39 PE8, 40 PE9, 41 PE10, 42 PE11, 43 PE12, 44 PE13, 45 PE14, 46 PE15, 47 PB10, 48 PB11, 51 PB12, 52 PB13, 53 PB14, 54 PB15, 55 PD8, 56 PD9, 57 PD10, 58 PD11, 59 PD12, 60 PD13, 61 PD14, 62 PD15, 63 PC6, 64 PC7, 65 PC8, 66 PC9, 67 PA8, 68 PA9, 69 PA10, 70 PA11, 71 PA12, 72 PA13, 73 PF6, 76 PA14, 77 PA15, 78 PC10, 79 PC11, 80 PC12, 81 PD0, 82 PD1, 83 PD2, 84 PD3, 85 PD4, 86 PD5, 87 PD6, 88 PD7, 89 PB3, 90 PB4, 91 PB5, 92 PB6, 93 PB7, 94 BOOT0, 95 PB8, 96 PB9, 97 PE0, 98 PE1
part B pins: 6 VBAT, 20 VSSadc/VREF-, 21 VREF+, 22 VDDadc, 28 VDD4, 49 VSS2, 50 VDD2, 74 VSS3, 75 VDD3, 99 VSSA_VSS1, 100 VDD1

## STPS340
designator D?
Default Diode; Code - JEDEC: DO-214-AB
footprint DSO-C2/X3.3 (DO-214-AB/SMC; 2 C-Bend Leads; Body 7.9 x 5.9 mm, inc. leads (LxW))
simulation model DIODE (Diode)
signal-integrity model Diode
footprint SOD-323 (Footprint not found)
footprint SMB (Footprint not found)
pins: 1 A, 2 K

## STT5PF20V
designator T?, comment FDC606P
footprint Model Name (Footprint not found)
footprint SOT23-6L
pins: 1 D, 2 D, 3 G, 4 S, 5 D, 6 D

## STTS751-0WB3F
designator U?
footprint SOT23-6L (Footprint not found)
pins: 1 Addr/~{Therm}, 2 GND, 3 VDD, 4 SCL, 5 ~{EVENT}, 6 SDA

## SW PUSHBUTTON
designator B?, comment TD-0341 [RESET/Black]
SE PUSHBUTTON
footprint PB (Footprint not found)
footprint PB10
pins: 1 A0, 2 B0, 3 B1, 4 A1

## SW-SPDT
designator SW?, comment 09.03290.01
SPDT Subminiature Toggle Switch, Right Angle Mounting, Vertical Actuation; Revision 1: Jul-2002: Re-released for DXP Platform.; Revision 2: 17-Dec-2003: Schematic revised, PCB Footprint replaced.
footprint SIP3 (Footprint not found)
pins: 1, 2, 3

## TFDU4300
designator U?, comment TFDU6300
TFDU4300
footprint IR_VISHAY3 (Footprint not found)
pins: 1 Anode (VCC2), 2 Cathode, 3 TxD (in), 4 RxD (out), 5 SD, 6 VCC1, 7 Vlogic, 8 GND
2 alternate drawings of the same symbol

## TP
designator TP?, comment 5V
footprint TP (Footprint not found)
pins: 1

## TS472IQT
designator U?
footprint QFN24 (Footprint not found)
footprint QFN24(4X4)
pins: 2 BYP, 4 GND, 5 IN-, 8 IN+, 9 GS, 10 BIAS, 14 C1, 15 C2, 16 OUT-, 17 OUT+, 20 VCC, 21 STBY, 22 GND

## TS_PAD
designator TS?
footprint Model Name (Footprint not found)
footprint TS_PAD
pins: 1

## TSOP34838
designator U?, comment TSOP34836
footprint TSOP348 (Footprint not found)
pins: 1 OUT, 2 GND, 3 Vs

## USB-B
designator CN?, comment USB-typeB connector
USB-B
footprint USB-B (Footprint not found)
pins: 0 SHELL, 0 SHELL, 1 VCC, 2 D-, 3 D+, 4 GND

## USB-typeB connector
designator CN?
footprint USB/B MINI
footprint USB-B
pins: 0 SHELL (power), 0 SHELL (power), 1 VCC (io), 2 D- (io), 3 D+ (io), 4 GND
2 alternate drawings of the same symbol

## USBLC6-2
designator U?, comment USBLC6-2P6 (optional)
footprint SOT-666 (Footprint not found)
pins: 1 I/O1, 2 GND, 3 I/O2, 4 I/O2, 5 Vbus, 6 I/O1

## VOLTREG1
designator U?, comment LD1086D2M33
footprint D2PAK/A (Footprint not found)
pins: 1 GND, 2 Vout, 3 Vin
2 alternate drawings of the same symbol

## XTAL
designator X?, comment 8MHz
Crystal Oscillator
footprint R38
footprint XTAL1
footprint SMT_XTAL
pins: 1 OSC1, 2 OSC2
2 alternate drawings of the same symbol

## ZEN056V130A24LS
designator U?
footprint polyzen (Footprint not found)
pins: 1, 2, 3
